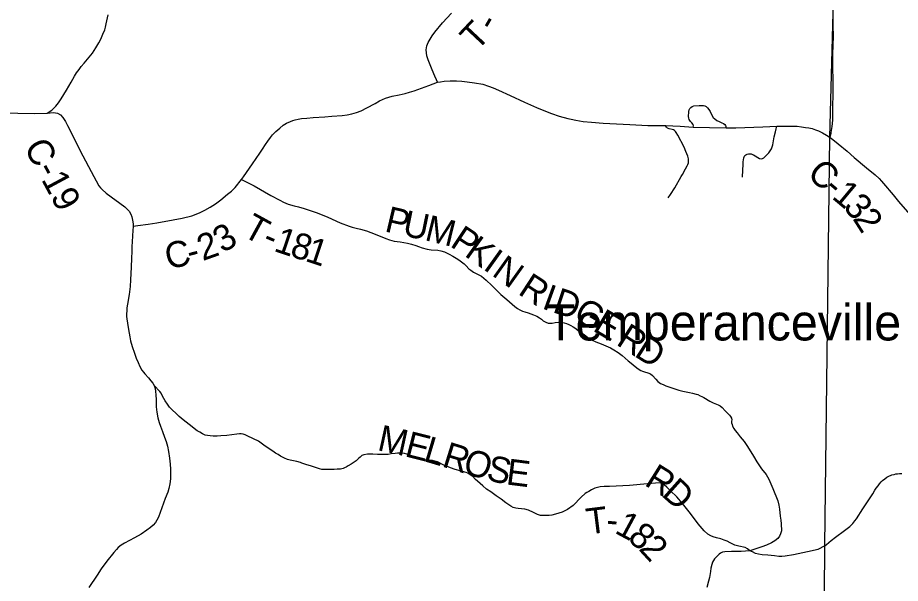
# Model space of a CAD drawing. Extents: x -10 to 158, y 8 to 33.
# Drawn here: x 151.875 to 153.801, y 26.374 to 27.608 of the extents above; entities that cross this region are included whole.
import ezdxf

# ---------------------------------------------------------------- set-up
doc = ezdxf.new("R2010")
doc.units = 0
for name, color, linetype in [('GM_X_County_Road', 7, 'Continuous'), ('GM_X_County_Road_Text', 7, 'Continuous'), ('GM_X_State_Route', 7, 'Continuous'), ('GM_X_Township_Road', 7, 'Continuous'), ('GM_X_Township_Road_Text', 7, 'Continuous'), ('GM_X_Township_Text', 7, 'Continuous'), ('GM_X_Unincorporated_Text', 7, 'Continuous')]:
    doc.layers.add(name, color=color, linetype=linetype)

msp = doc.modelspace()

# ---------------------------------------------------------------- linework, layer by layer
at = {"layer": 'GM_X_County_Road'}
for points in [[(152.1268, 27.1534), (152.1374, 27.1547), (152.1596, 27.1575), (152.1783, 27.1604), (152.2141, 27.1667), (152.2338, 27.1706), (152.2553, 27.176), (152.2641, 27.1794), (152.2734, 27.1832), (152.2832, 27.1883), (152.2948, 27.1948), (152.3063, 27.2021), (152.318, 27.2105), (152.3331, 27.2227), (152.3413, 27.2297), (152.3493, 27.2374), (152.3637, 27.2552), (152.3674, 27.2606), (152.3876, 27.2894), (152.4036, 27.3128), (152.409, 27.3211), (152.416, 27.3314), (152.4209, 27.339), (152.4265, 27.3466), (152.4313, 27.3525), (152.4379, 27.3596), (152.4468, 27.3673), (152.4543, 27.3733), (152.4616, 27.3779), (152.4703, 27.3818), (152.4751, 27.3834), (152.4806, 27.3849), (152.4872, 27.3865), (152.4943, 27.3878), (152.506, 27.389), (152.5196, 27.39), (152.5452, 27.3918), (152.5602, 27.393), (152.583, 27.3949), (152.5937, 27.3964), (152.6043, 27.3985), (152.6141, 27.4014), (152.6244, 27.405), (152.6371, 27.4111), (152.6547, 27.4212), (152.6643, 27.4267), (152.6711, 27.4297), (152.6774, 27.4323), (152.6924, 27.4368), (152.7075, 27.4399), (152.7201, 27.4429), (152.73, 27.4457), (152.7399, 27.4488), (152.7717, 27.46), (152.7906, 27.4671), (152.7974, 27.4682), (152.8057, 27.4694), (152.8183, 27.4705), (152.8321, 27.47), (152.844, 27.4694), (152.8558, 27.4684), (152.8717, 27.4663), (152.8902, 27.4628), (152.9025, 27.4589), (152.9121, 27.455), (152.924, 27.4498), (152.9496, 27.4382), (152.9804, 27.4239), (153.0069, 27.4123), (153.0227, 27.4053), (153.0397, 27.3989), (153.0567, 27.3935), (153.0752, 27.3884), (153.0825, 27.3866), (153.0926, 27.3843), (153.1085, 27.3818), (153.127, 27.3798), (153.1522, 27.3777), (153.2109, 27.3748), (153.2495, 27.3729), (153.2886, 27.3727), (153.3205, 27.3711), (153.3485, 27.3694), (153.3845, 27.3684), (153.4208, 27.3677), (153.442, 27.3681), (153.501, 27.3697), (153.5314, 27.3713), (153.5609, 27.3716), (153.5753, 27.3711), (153.5853, 27.3701), (153.5941, 27.3687), (153.6013, 27.3677), (153.6083, 27.3661), (153.6155, 27.3636), (153.6222, 27.361), (153.6309, 27.3568), (153.6394, 27.3518), (153.6474, 27.3466)], [(151.9392, 27.3999), (151.9533, 27.4012), (151.9617, 27.3995), (151.9683, 27.3961), (151.9738, 27.3905), (151.9791, 27.3813), (151.9839, 27.373), (152.017, 27.3068), (152.0351, 27.2721), (152.0523, 27.2414), (152.0556, 27.237), (152.0595, 27.2328), (152.0678, 27.2252), (152.1088, 27.1951), (152.1139, 27.1904), (152.1181, 27.186), (152.122, 27.1793), (152.1241, 27.1735), (152.1259, 27.1659), (152.1267, 27.1584), (152.1268, 27.1534), (152.1256, 27.133), (152.1247, 27.1184), (152.1244, 27.1096), (152.1239, 27.0975), (152.1233, 27.0836), (152.1223, 27.0639), (152.1214, 27.036), (152.1203, 27.0215), (152.1182, 27.0041), (152.1147, 26.9831), (152.1135, 26.9752), (152.113, 26.9688), (152.1126, 26.9614), (152.1128, 26.9557), (152.1152, 26.9363), (152.118, 26.9198), (152.1195, 26.9113), (152.1213, 26.9027), (152.1248, 26.8908), (152.1296, 26.8761), (152.1337, 26.8653), (152.1378, 26.8555), (152.1417, 26.8468), (152.1462, 26.8386), (152.1493, 26.8344), (152.1522, 26.8307), (152.1603, 26.8219), (152.1658, 26.8153), (152.1697, 26.8103), (152.1728, 26.8054), (152.175, 26.7988), (152.1761, 26.7926), (152.1766, 26.7851), (152.1769, 26.7742), (152.1774, 26.7587), (152.1787, 26.7469), (152.1808, 26.7345), (152.1836, 26.7249), (152.1863, 26.7169), (152.1886, 26.7109), (152.191, 26.7052), (152.1957, 26.6926), (152.1988, 26.6831), (152.2016, 26.6727), (152.2039, 26.6616), (152.206, 26.647), (152.2079, 26.6335), (152.2085, 26.6231), (152.2085, 26.6025), (152.208, 26.5959), (152.2071, 26.5905), (152.2048, 26.5806), (152.2023, 26.5729), (152.1969, 26.5588), (152.1821, 26.5181), (152.179, 26.5114), (152.1759, 26.5066), (152.1707, 26.5007), (152.165, 26.4955), (152.1571, 26.4893), (152.1446, 26.4812), (152.1302, 26.473), (152.1188, 26.4672), (152.108, 26.4615), (152.1006, 26.4571), (152.0943, 26.4516), (152.0903, 26.4474), (152.0845, 26.4408), (152.0699, 26.4221), (152.0573, 26.4053), (152.0483, 26.3913), (152.0306, 26.3644)], [(153.6474, 27.3466), (153.6535, 27.3422), (153.6648, 27.3329), (153.6847, 27.3166), (153.6998, 27.3033), (153.727, 27.2808), (153.7456, 27.2652), (153.7543, 27.2573), (153.7598, 27.2515), (153.7642, 27.2464), (153.7849, 27.2216), (153.7969, 27.2069), (153.8164, 27.1843), (153.8291, 27.169), (153.8335, 27.1635), (153.8411, 27.1534)]]:
    msp.add_lwpolyline(points, dxfattribs=at)
at = {"layer": 'GM_X_State_Route'}
msp.add_lwpolyline([(151.8389, 27.4006), (151.8753, 27.4001), (151.9125, 27.3993), (151.9392, 27.3999), (151.9499, 27.4062), (151.9582, 27.4147), (151.9641, 27.4225), (151.9698, 27.431), (151.9813, 27.4499), (151.9915, 27.4675), (151.9991, 27.4804), (152.0037, 27.4879), (152.0089, 27.4951), (152.0136, 27.5015), (152.0198, 27.5091), (152.0382, 27.5307), (152.0459, 27.542), (152.0523, 27.5534), (152.0566, 27.5615), (152.0611, 27.5722), (152.0651, 27.5817), (152.067, 27.5874), (152.0684, 27.5945), (152.0723, 27.6146)], dxfattribs=at)
at = {"layer": 'GM_X_Township_Road'}
for points in [[(152.7906, 27.4671), (152.7888, 27.4722), (152.7848, 27.4805), (152.7793, 27.4944), (152.7734, 27.5087), (152.7704, 27.5159), (152.7677, 27.5248), (152.7666, 27.5315), (152.7664, 27.538), (152.768, 27.547), (152.7707, 27.5539), (152.7749, 27.5611), (152.7794, 27.5682), (152.7855, 27.5764), (152.8022, 27.5971), (152.8218, 27.6177)], [(153.6474, 27.3466), (153.6495, 27.3552), (153.6498, 27.3577), (153.6522, 27.3704), (153.6529, 27.3769), (153.6532, 27.3852), (153.6534, 27.4168), (153.654, 27.438), (153.6538, 27.4672), (153.6534, 27.5038), (153.6535, 27.5268), (153.6541, 27.5498), (153.6546, 27.5664), (153.6544, 27.5924), (153.6543, 27.615)], [(153.3485, 27.3694), (153.3493, 27.3724), (153.3485, 27.3749), (153.3461, 27.3784), (153.343, 27.3814), (153.3403, 27.3858), (153.3395, 27.3885), (153.3388, 27.3923), (153.3387, 27.3957), (153.339, 27.3997), (153.3395, 27.4033), (153.3403, 27.4067), (153.3417, 27.4102), (153.3437, 27.4122), (153.3464, 27.4142), (153.35, 27.4156), (153.3621, 27.4163), (153.3711, 27.4165), (153.3742, 27.4158), (153.3773, 27.4143), (153.3803, 27.4116), (153.3832, 27.4079), (153.3857, 27.4037), (153.3898, 27.3955), (153.3927, 27.3906), (153.3962, 27.3872), (153.4007, 27.3839), (153.4053, 27.3814), (153.4114, 27.3788), (153.4152, 27.3769), (153.4179, 27.3747), (153.4193, 27.3726), (153.4208, 27.3677)], [(153.2939, 27.2149), (153.2993, 27.2224), (153.3084, 27.2365), (153.3226, 27.2614), (153.3253, 27.266), (153.3323, 27.2783), (153.3353, 27.2848), (153.3369, 27.2877), (153.3382, 27.2916), (153.3387, 27.2954), (153.3384, 27.3002), (153.337, 27.3061), (153.333, 27.3162), (153.3289, 27.3258), (153.3152, 27.352), (153.3118, 27.3575), (153.3099, 27.3601), (153.3078, 27.3619), (153.3056, 27.3635), (153.3031, 27.3644), (153.2967, 27.3658), (153.293, 27.3667), (153.2906, 27.369), (153.2886, 27.3727)], [(153.4563, 27.2604), (153.4573, 27.2754), (153.4575, 27.2877), (153.4577, 27.2936), (153.4582, 27.2981), (153.4592, 27.3026), (153.4602, 27.3048), (153.4618, 27.3073), (153.4639, 27.3087), (153.4667, 27.3102), (153.4692, 27.3109), (153.4724, 27.311), (153.4749, 27.3107), (153.4781, 27.3098), (153.4806, 27.3085), (153.4839, 27.3066), (153.4899, 27.3027), (153.4936, 27.301), (153.4971, 27.3003), (153.5003, 27.3008), (153.5029, 27.3021), (153.5075, 27.3067), (153.5135, 27.3132), (153.5166, 27.3174), (153.5196, 27.322), (153.5213, 27.3266), (153.5225, 27.3308), (153.5256, 27.3478), (153.5281, 27.3592), (153.5298, 27.3653), (153.5305, 27.3683), (153.5314, 27.3713)], [(152.3637, 27.2552), (152.3912, 27.241), (152.4273, 27.2201), (152.447, 27.2099), (152.4551, 27.2056), (152.46, 27.2035), (152.4653, 27.2013), (152.4779, 27.1977), (152.4877, 27.1952), (152.5004, 27.192), (152.5282, 27.1822), (152.5518, 27.1727), (152.5785, 27.1607), (152.5986, 27.1532), (152.6049, 27.1511), (152.6137, 27.1486), (152.6228, 27.1464), (152.6361, 27.1427), (152.6458, 27.1393), (152.6587, 27.1342), (152.6783, 27.126), (152.6862, 27.1232), (152.6967, 27.1205), (152.7095, 27.1186), (152.7256, 27.1158), (152.7344, 27.1137), (152.7434, 27.1113), (152.7495, 27.1091), (152.7577, 27.1061), (152.7685, 27.1029), (152.7725, 27.1019), (152.7773, 27.1014), (152.7919, 27.101), (152.7983, 27.0995), (152.8059, 27.0972), (152.8166, 27.0922), (152.8247, 27.0876), (152.8314, 27.0835), (152.8372, 27.0796), (152.8436, 27.0751), (152.849, 27.0709), (152.8533, 27.0663), (152.8593, 27.0602), (152.8634, 27.057), (152.8697, 27.0529), (152.8867, 27.0439), (152.8971, 27.0354), (152.9096, 27.0235), (152.9294, 27.0038), (152.9421, 26.9928), (152.9595, 26.9776), (152.9652, 26.9736), (152.9706, 26.9705), (152.9761, 26.9679), (152.9818, 26.966), (152.9885, 26.964), (153.0005, 26.9598), (153.0074, 26.9569), (153.0138, 26.9534), (153.018, 26.9499), (153.0218, 26.9467), (153.0275, 26.9435), (153.0327, 26.9416), (153.0363, 26.9413), (153.041, 26.9416), (153.048, 26.9427), (153.0545, 26.9433), (153.0608, 26.9431), (153.0674, 26.942), (153.0722, 26.9407), (153.0772, 26.9386), (153.0822, 26.9361), (153.0868, 26.9336), (153.0907, 26.9312), (153.0974, 26.9264), (153.1115, 26.9162), (153.1185, 26.9109), (153.1271, 26.9054), (153.1363, 26.9007), (153.1478, 26.8962), (153.1683, 26.8878), (153.1757, 26.8833), (153.1848, 26.8772), (153.1935, 26.8708), (153.2071, 26.8594), (153.2137, 26.8538), (153.2221, 26.8469), (153.2285, 26.842), (153.2348, 26.8382), (153.2385, 26.8366), (153.2427, 26.8353), (153.25, 26.8331), (153.2557, 26.8305), (153.2598, 26.8273), (153.2674, 26.8193), (153.2718, 26.8143), (153.2778, 26.8098), (153.2831, 26.8073), (153.2892, 26.8049), (153.298, 26.8015), (153.3106, 26.7974), (153.3176, 26.7954), (153.3262, 26.7932), (153.3407, 26.7899), (153.3476, 26.7886), (153.3551, 26.7866), (153.3588, 26.7854), (153.364, 26.7831), (153.3678, 26.7815), (153.372, 26.7793), (153.385, 26.7715), (153.3927, 26.7679), (153.4031, 26.7634), (153.4075, 26.7607), (153.4117, 26.7573), (153.4182, 26.7504), (153.4232, 26.7457), (153.4281, 26.7408), (153.4305, 26.7375), (153.432, 26.7341), (153.4329, 26.7306), (153.4327, 26.7277), (153.4327, 26.7236), (153.4336, 26.7199), (153.4344, 26.7167), (153.4374, 26.7115), (153.4407, 26.7069), (153.4444, 26.7018), (153.451, 26.6936), (153.4598, 26.683), (153.4672, 26.6722), (153.4801, 26.651), (153.4876, 26.6389), (153.498, 26.6234), (153.5077, 26.611), (153.5141, 26.6008), (153.5225, 26.5809), (153.5334, 26.5536), (153.5353, 26.544), (153.5368, 26.5356), (153.5383, 26.5204), (153.5397, 26.5118), (153.541, 26.5037), (153.5415, 26.4883), (153.5395, 26.4815), (153.5374, 26.4768), (153.5331, 26.4714), (153.5267, 26.4666), (153.5193, 26.4621), (153.5086, 26.4569), (153.4983, 26.453), (153.4722, 26.4448), (153.4536, 26.4433), (153.432, 26.4434), (153.4181, 26.4424), (153.4125, 26.4413), (153.4086, 26.4397), (153.4056, 26.4376), (153.4, 26.432), (153.3951, 26.427), (153.3911, 26.4195), (153.3893, 26.4147), (153.3876, 26.4064), (153.3869, 26.3995), (153.3842, 26.3861), (153.3823, 26.3785), (153.3782, 26.3648)], [(152.6278, 26.6531), (152.6262, 26.6524), (152.622, 26.649), (152.6186, 26.6457), (152.6132, 26.641), (152.6089, 26.638), (152.6027, 26.6335), (152.5964, 26.6297), (152.5917, 26.6271), (152.5881, 26.6255), (152.5851, 26.6245), (152.5791, 26.6231), (152.5724, 26.6225), (152.5656, 26.622), (152.5538, 26.6218), (152.544, 26.622), (152.5385, 26.6224), (152.5335, 26.6232), (152.5288, 26.6248), (152.5136, 26.63), (152.5058, 26.6324), (152.4997, 26.6344), (152.4953, 26.636), (152.4919, 26.6372), (152.4844, 26.6394), (152.4766, 26.6409), (152.4697, 26.6424), (152.4635, 26.6441), (152.4572, 26.6466), (152.4487, 26.651), (152.443, 26.6545), (152.4376, 26.6578), (152.4315, 26.662), (152.415, 26.6731), (152.4005, 26.6837), (152.3771, 26.6951), (152.3712, 26.6976), (152.3669, 26.6991), (152.3626, 26.6998), (152.3588, 26.6998), (152.3534, 26.6995), (152.3311, 26.6963), (152.3184, 26.6955), (152.31, 26.6951), (152.3013, 26.6949), (152.2947, 26.6953), (152.289, 26.696), (152.284, 26.6972), (152.278, 26.6997), (152.2721, 26.7033), (152.2669, 26.7065), (152.2494, 26.7201), (152.2426, 26.7252), (152.2359, 26.7305), (152.2276, 26.7377), (152.2206, 26.7442), (152.2123, 26.7522), (152.2066, 26.7583), (152.2019, 26.7643), (152.1969, 26.772), (152.1941, 26.7771), (152.1899, 26.7851), (152.188, 26.7885), (152.185, 26.7922), (152.1728, 26.8054)], [(153.4722, 26.4448), (153.467, 26.4491), (153.4624, 26.4515), (153.4483, 26.4546), (153.4396, 26.4569), (153.4297, 26.4617), (153.4227, 26.4654), (153.4166, 26.468), (153.4094, 26.4705), (153.3995, 26.4731), (153.3925, 26.4751), (153.3876, 26.4772), (153.3809, 26.4808), (153.373, 26.4883), (153.3593, 26.5036), (153.3432, 26.5257), (153.3256, 26.548), (153.3128, 26.5626), (153.2994, 26.5757), (153.2912, 26.5837), (153.2853, 26.5886), (153.2806, 26.5912), (153.2751, 26.5931), (153.2491, 26.5905), (153.2097, 26.5869), (153.1662, 26.5852), (153.1543, 26.585), (153.1459, 26.5842), (153.1344, 26.5812), (153.127, 26.5776), (153.1211, 26.5742), (153.1164, 26.5717), (153.1133, 26.5695), (153.1044, 26.5614), (153.0872, 26.5433), (153.0749, 26.535), (153.0632, 26.5289), (153.0486, 26.5245), (153.0407, 26.5226), (153.0347, 26.5214), (153.0294, 26.5213), (153.0218, 26.5213), (153.0158, 26.5219), (153.009, 26.5239), (153.0002, 26.5281), (152.9894, 26.5335), (152.9812, 26.5355), (152.9744, 26.5361), (152.9671, 26.5369), (152.9621, 26.5377), (152.9563, 26.5392), (152.9506, 26.5419), (152.9401, 26.549), (152.9301, 26.5571), (152.9192, 26.5646), (152.9074, 26.5732), (152.8982, 26.5794), (152.8899, 26.5863), (152.8838, 26.5918), (152.878, 26.5967), (152.8741, 26.6004), (152.8677, 26.6065), (152.8603, 26.6118), (152.8568, 26.6139), (152.8536, 26.6153), (152.8406, 26.6192), (152.8298, 26.6222), (152.8194, 26.6256), (152.8032, 26.6324), (152.7907, 26.6385), (152.7848, 26.6405), (152.7798, 26.6416), (152.771, 26.6426), (152.7615, 26.6427), (152.7575, 26.643), (152.7533, 26.6436), (152.7495, 26.6448), (152.7444, 26.6466), (152.7308, 26.6529), (152.7238, 26.6557), (152.7188, 26.657), (152.7145, 26.6577), (152.7085, 26.6578), (152.7037, 26.6575), (152.6986, 26.657), (152.6902, 26.6559), (152.6831, 26.655), (152.6747, 26.6546), (152.6663, 26.6546), (152.6597, 26.6547), (152.6499, 26.6552), (152.6386, 26.6553), (152.6303, 26.654), (152.6278, 26.6531)], [(153.6359, 26.4556), (153.6394, 26.4584), (153.6496, 26.4669), (153.6594, 26.4743), (153.6786, 26.4891), (153.6904, 26.4978), (153.6928, 26.5001), (153.6969, 26.5044), (153.7017, 26.5103), (153.7047, 26.5146), (153.7192, 26.5364), (153.7404, 26.5691), (153.745, 26.5768), (153.7483, 26.5815), (153.752, 26.5864), (153.7554, 26.5906), (153.7592, 26.5948), (153.762, 26.5977), (153.7666, 26.6017), (153.7715, 26.6051), (153.7768, 26.608), (153.7795, 26.6092), (153.7825, 26.6103), (153.787, 26.6114), (153.7912, 26.6123), (153.7945, 26.6128), (153.7991, 26.6133), (153.8037, 26.6135)], [(153.6359, 26.4556), (153.6209, 26.4474), (153.6152, 26.4458), (153.5985, 26.4422), (153.588, 26.44), (153.5674, 26.4355), (153.5495, 26.4328), (153.5421, 26.4322), (153.5356, 26.4324), (153.5265, 26.4336), (153.5113, 26.4351), (153.4993, 26.436), (153.491, 26.4373), (153.4845, 26.4388), (153.4784, 26.4421), (153.4722, 26.4448)]]:
    msp.add_lwpolyline(points, dxfattribs=at)
at = {"layer": 'GM_X_Township_Text'}
msp.add_lwpolyline([(153.6265, 25.0623), (153.6357, 26.4561), (153.6472, 27.3472), (153.6542, 27.6186), (153.661, 28.3755), (153.6842, 29.1862), (153.6856, 29.293), (153.6884, 29.4756), (153.6987, 29.8088), (153.7008, 29.9089), (153.703, 29.918), (153.6996, 30.0615), (153.6575, 30.0619)], dxfattribs=at)

# ---------------------------------------------------------------- texts
at = {"layer": 'GM_X_County_Road_Text'}
for s, height, rotation, p in [('C-19', 0.05682, 298.2545, (151.8877, 27.326)), ('C', 0.0568, 317.4404, (153.5947, 27.2639)), ('-', 0.0568, 319.682, (153.6309, 27.2308)), ('1', 0.0568, 320.1295, (153.649, 27.2153)), ('3', 0.0568, 310.2976, (153.6741, 27.1947)), ('2', 0.0568, 302.4516, (153.6955, 27.1697)), ('3', 0.0568, 30.5897, (152.3224, 27.0935)), ('2', 0.0568, 19.5484, (152.2786, 27.0767)), ('C', 0.0568, 12.4183, (152.203, 27.0585)), ('-', 0.0568, 14.9304, (152.2513, 27.0692))]:
    msp.add_text(s, height=height, rotation=rotation, dxfattribs=at).set_placement(p)
at = {"layer": 'GM_X_Township_Road_Text'}
for s, rotation, p in [('T', 46.8124, (152.8767, 27.5336)), ('-', 59.6296, (152.9141, 27.5757)), ('P', 346.8903, (152.6736, 27.142)), ('T', 331.2438, (152.3631, 27.1335)), ('U', 348.4336, (152.7125, 27.1329)), ('M', 346.2188, (152.7609, 27.123)), ('P', 326.4694, (152.8161, 27.1104)), ('1', 341.1997, (152.4317, 27.0996)), ('8', 343.199, (152.4669, 27.0877)), ('-', 337.1172, (152.4061, 27.1103)), ('1', 341.7329, (152.5001, 27.0777)), ('K', 324.5284, (152.8476, 27.0895)), ('I', 324.4714, (152.8884, 27.0605)), ('N', 324.4739, (152.9073, 27.047)), ('R', 326.8846, (152.9644, 27.0063)), ('I', 340.1701, (153.0164, 26.9744)), ('D', 341.4655, (153.0397, 26.966)), ('G', 329.6872, (153.0843, 26.9514)), ('E', 329.2222, (153.1273, 26.9262)), ('R', 327.6479, (153.1785, 26.8957)), ('D', 327.5204, (153.2179, 26.8707)), ('M', 347.6016, (152.6577, 26.6646)), ('E', 345.7361, (152.7174, 26.6514)), ('L', 343.4695, (152.7581, 26.6411)), ('R', 342.6944, (152.7986, 26.6291)), ('O', 343.2581, (152.8437, 26.615)), ('S', 346.7114, (152.8952, 26.5997)), ('E', 352.8017, (152.939, 26.5897)), ('R', 327.8722, (153.2402, 26.5891)), ('D', 318.4022, (153.2777, 26.5658)), ('T', 7.0681, (153.1187, 26.48)), ('1', 331.7451, (153.1752, 26.4848)), ('-', 354.9434, (153.1577, 26.4852)), ('8', 318.0043, (153.2031, 26.4703)), ('2', 312.7253, (153.2281, 26.4479))]:
    msp.add_text(s, height=0.0568, rotation=rotation, dxfattribs=at).set_placement(p)
at = {"layer": 'GM_X_Unincorporated_Text'}
msp.add_text('Temperanceville', height=0.078977, rotation=0, dxfattribs=at).set_placement((153.0277, 26.9037))

doc.saveas('drawing.dxf')
